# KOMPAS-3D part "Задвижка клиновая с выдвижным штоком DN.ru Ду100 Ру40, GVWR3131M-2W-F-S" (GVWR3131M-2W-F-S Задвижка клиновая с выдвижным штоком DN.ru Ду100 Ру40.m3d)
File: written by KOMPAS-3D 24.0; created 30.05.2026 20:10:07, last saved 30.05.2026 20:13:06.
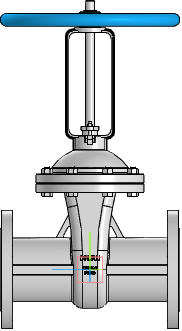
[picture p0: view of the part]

Document properties: Автор: R2D2; Полное имя файла: E:\Работа\Зайцев\GVWR3131M-2W-F-S Задвижка клиновая с выдвижным штоком DN.ru Ду50-100 Ру40\исходные материалы\DN100\DN100\GVWR3131M-2W-F-S Задвижка клиновая с выдвижным штоком DN.ru Ду100 Ру40.m3d

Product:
- Part/product: Задвижка клиновая с выдвижным штоком DN.ru Ду100 Ру40  | designation GVWR3131M-2W-F-S
    Масса: 39
    Раздел спецификации: Прочие изделия
    Примечание: D040-09952

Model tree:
1. Операция без истории:1

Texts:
  GVWR3131M-2W-F-S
